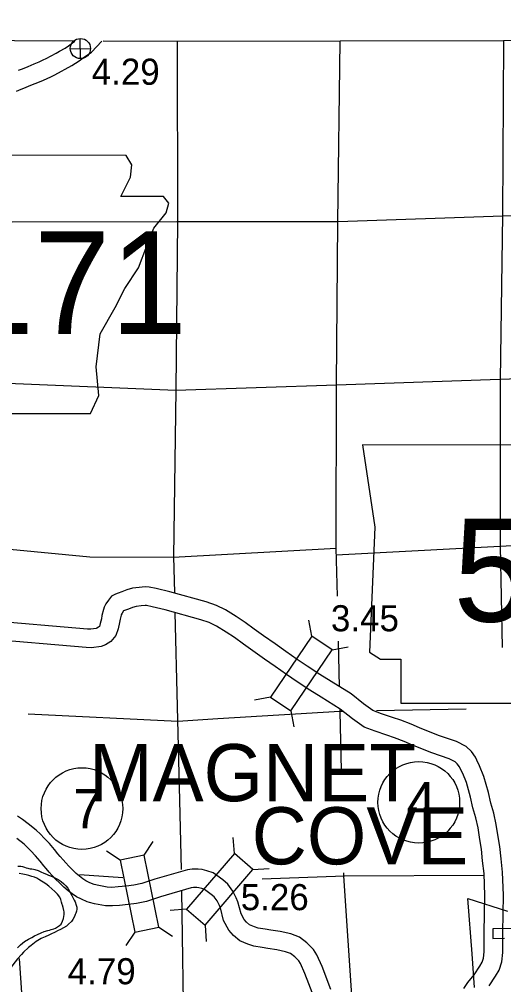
# Model space of a CAD drawing. Extents: x 369523 to 838377, y 495025 to 936819.
# Drawn here: x 644076 to 659736, y 887609 to 918834 of the extents above; entities that cross this region are included whole.
import ezdxf

# ---------------------------------------------------------------- set-up
doc = ezdxf.new("R2010")
doc.units = 0
for name, color, linetype in [('22', 7, 'Continuous'), ('DSN_BRDG_Annotation', 7, 'Continuous'), ('DSN_DRFT_Common-Annotations', 7, 'Continuous'), ('DSN_DRFT_Common-Line', 7, 'Continuous'), ('DSN_DRFT_Junk-No-Plot', 7, 'Continuous'), ('Level 1', 7, 'Continuous'), ('Level 10', 7, 'Continuous'), ('Level 11', 7, 'Continuous'), ('Level 2', 7, 'Continuous'), ('Level 21', 7, 'Continuous'), ('Level 22', 7, 'Continuous'), ('Level 6', 7, 'Continuous')]:
    doc.layers.add(name, color=color, linetype=linetype)

msp = doc.modelspace()

# ---------------------------------------------------------------- linework, layer by layer
at = {"layer": '22'}
for points in [[(639541, 914438), (639941, 911773), (639763, 907732), (640118, 907510), (640784, 907510), (640784, 906089), (646380, 906089), (646646, 906666), (646558, 907598), (646691, 908664), (647179, 909508), (647490, 910130), (647934, 910796), (648201, 911507), (648423, 912084), (648822, 912572), (648911, 912883), (648734, 913105), (647357, 913105), (647668, 913727), (647712, 914127), (647528, 914434)], [(655173, 905068), (655572, 902403), (655395, 898362), (655750, 898140), (656416, 898140), (656416, 896719), (662012, 896719), (662278, 897296), (662189, 898229), (662323, 899295), (662811, 900138), (663122, 900760), (663566, 901426), (663832, 902137), (664055, 902714), (664454, 903203), (664543, 903513), (664365, 903735), (662989, 903735), (663300, 904357), (663344, 904757), (663160, 905064)]]:
    msp.add_lwpolyline(points, close=True, dxfattribs=at)
at = {"layer": 'DSN_DRFT_Common-Annotations'}
for p, q in [((646058, 917562), (646043, 918213)), ((645725, 917880), (646376, 917895))]:
    msp.add_line(p, q, dxfattribs=at)
msp.add_circle((646051, 917888), 326, dxfattribs=at)
at = {"layer": 'DSN_DRFT_Common-Line'}
for centre in [(646101, 893305), (656992, 893507)]:
    msp.add_circle(centre, 1320, dxfattribs=at)
at = {"layer": 'Level 1'}
for points in [[(645269, 917739), (645370, 917808), (645554, 917900), (645662, 917976), (645792, 918071), (645876, 918130)], [(645775, 917343), (646011, 917488), (646143, 917584), (646405, 917771), (646745, 918131)], [(644052, 917189), (644176, 917236), (644357, 917312), (644551, 917391), (644716, 917458), (644850, 917519), (644942, 917567), (645269, 917739)], [(643984, 916511), (644136, 916574), (644274, 916632), (644398, 916678), (644586, 916757), (644778, 916835), (644953, 916906), (645114, 916980), (645227, 917039), (645775, 917343)], [(659265, 887577), (659471, 887889), (659587, 888081), (659678, 888348), (659703, 888647), (659710, 889295), (659728, 890502), (659701, 891248), (659653, 891680), (659609, 892077), (659558, 892395), (659496, 892791), (659415, 893157), (659324, 893482), (659247, 893823), (659099, 894348), (658958, 894691), (658871, 894867), (658820, 894969), (658693, 895149), (658520, 895315), (658208, 895470), (657628, 895670), (657018, 895916), (656744, 896033), (656412, 896164), (656141, 896252), (655785, 896372), (655510, 896477), (655204, 896689), (654803, 897012), (654158, 897417), (653795, 897646), (653384, 897908), (653055, 898132), (652697, 898388), (652345, 898631), (651975, 898895), (651674, 899108), (651379, 899327), (651085, 899523), (650737, 899729), (650453, 899875), (650119, 899989), (648946, 900313), (648503, 900420), (648276, 900465), (648145, 900477), (647951, 900460), (647739, 900431), (647548, 900382), (647394, 900321), (647268, 900274), (647186, 900243), (647054, 900173), (646954, 900047), (646874, 899923), (646824, 899817), (646796, 899748), (646746, 899554), (646729, 899443), (646691, 899287), (646663, 899200), (646638, 899170), (646586, 899138), (646562, 899128), (646386, 899104), (646279, 899111), (643003, 899392)], [(658448, 887488), (658579, 887678), (658779, 887930), (658964, 888210), (659039, 888335), (659086, 888472), (659103, 888675), (659110, 889302), (659127, 890496), (659102, 891204), (659056, 891614), (659015, 891997), (658965, 892301), (658906, 892680), (658833, 893011), (658742, 893335), (658665, 893675), (658531, 894152), (658411, 894443), (658333, 894600), (658304, 894660), (658236, 894756), (658170, 894819), (657976, 894916), (657418, 895107), (656788, 895362), (656516, 895478), (656210, 895599), (655953, 895682), (655582, 895807), (655228, 895942), (654845, 896209), (654454, 896522), (653838, 896909), (653473, 897139), (653054, 897407), (652712, 897639), (652352, 897897), (652000, 898140), (651628, 898406), (651322, 898622), (651034, 898836), (650766, 899015), (650448, 899204), (650218, 899321), (649942, 899415), (648796, 899732), (648374, 899834), (648191, 899871), (648145, 899874), (648017, 899863), (647854, 899841), (647735, 899811), (647609, 899760), (647477, 899712), (647444, 899699), (647442, 899697), (647399, 899630), (647374, 899577), (647368, 899562), (647335, 899433), (647318, 899326), (647269, 899124), (647198, 898904), (647037, 898712), (646861, 898602), (646719, 898544), (646409, 898502), (646236, 898512), (642938, 898796)]]:
    msp.add_lwpolyline(points, dxfattribs=at)
at = {"layer": 'Level 10'}
for points in [[(644019, 888797), (644117, 888895), (644239, 889005), (644372, 889079), (644479, 889139), (644570, 889188), (644659, 889236), (644778, 889290), (644876, 889331), (644999, 889359), (645055, 889376), (645105, 889391), (645194, 889416), (645250, 889441), (645309, 889480), (645372, 889527), (645424, 889572), (645474, 889663), (645501, 889748), (645512, 889814), (645521, 889878), (645526, 889961), (645519, 890013), (645490, 890104), (645470, 890180), (645464, 890206), (645445, 890274), (645420, 890366), (645384, 890437), (645309, 890542), (645222, 890627), (645126, 890710), (645035, 890793), (644930, 890875), (644710, 891008), (644640, 891053), (644569, 891082), (644485, 891109), (644382, 891143), (644294, 891164), (644194, 891182), (644071, 891208)], [(644024, 891448), (644130, 891440), (644178, 891434), (644246, 891411), (644301, 891392), (644347, 891375), (644381, 891363), (644427, 891356), (644479, 891355), (644531, 891350), (644577, 891336), (644686, 891302), (644776, 891261), (644873, 891217), (644951, 891184), (645024, 891155), (645080, 891134), (645158, 891099), (645227, 891066), (645330, 891013), (645429, 890947), (645510, 890876), (645577, 890809), (645642, 890726), (645689, 890654), (645734, 890571), (645777, 890489), (645819, 890410), (645854, 890340), (645882, 890285), (645918, 890183), (645931, 890121), (645932, 890051), (645921, 889991), (645900, 889922), (645883, 889882), (645856, 889811), (645809, 889718), (645758, 889650), (645668, 889562), (645605, 889505), (645506, 889443), (645403, 889390), (645315, 889346), (645238, 889311), (645093, 889248)], [(645093, 889248), (645025, 889215), (644908, 889161), (644801, 889116), (644779, 889099), (644623, 889007), (644459, 888882), (644376, 888813), (644216, 888664), (644142, 888585), (644018, 888442), (643941, 888347), (643869, 888252), (643732, 888067), (643652, 887958), (643600, 887819), (643573, 887734), (643535, 887625), (643512, 887533)]]:
    msp.add_lwpolyline(points, dxfattribs=at)
at = {"layer": 'Level 11'}
for points in [[(654152, 887459), (653862, 888200), (653700, 888573), (653591, 888752), (653376, 888964), (653133, 889148), (652854, 889250), (652510, 889331), (652209, 889374), (652023, 889410), (651802, 889440), (651675, 889484), (651522, 889545), (651425, 889628), (651345, 889716), (651244, 889906), (651145, 890286), (651090, 890418), (650984, 890629), (650821, 890856), (650653, 891001), (650338, 891227), (650141, 891296), (649986, 891331), (649854, 891349), (649667, 891349), (649508, 891328), (648455, 891019), (648035, 890877), (647774, 890824), (647534, 890797), (647268, 890772), (647067, 890758), (646920, 890760), (646642, 890813), (646499, 890853), (646463, 890862), (646336, 890917), (646229, 890970), (646129, 891038), (646024, 891115), (645918, 891205), (645804, 891316), (645678, 891441), (645579, 891548), (645494, 891643), (645398, 891760), (645320, 891846), (645209, 891981), (645047, 892179), (644882, 892350), (644763, 892477), (644625, 892610), (644366, 892814), (644179, 892954), (644020, 893065)], [(653623, 887165), (653307, 887971), (653167, 888296), (653117, 888377), (652983, 888509), (652843, 888615), (652682, 888674), (652398, 888741), (652110, 888782), (651926, 888817), (651661, 888854), (651466, 888922), (651210, 889023), (651005, 889197), (650850, 889370), (650681, 889686), (650575, 890095), (650545, 890168), (650469, 890317), (650375, 890448), (650281, 890529), (650058, 890689), (649976, 890718), (649878, 890740), (649813, 890749), (649705, 890749), (649632, 890740), (648636, 890446), (648192, 890297), (647868, 890231), (647595, 890200), (647318, 890174), (647084, 890157), (646859, 890161), (646507, 890228), (646344, 890273), (646267, 890293), (646083, 890373), (645927, 890450), (645782, 890548), (645651, 890645), (645515, 890761), (645383, 890888), (645246, 891024), (645135, 891145), (645038, 891253), (644944, 891368), (644866, 891454), (644746, 891601), (644598, 891780), (644447, 891937), (644335, 892056), (644231, 892157), (644000, 892338)]]:
    msp.add_lwpolyline(points, dxfattribs=at)
at = {"layer": 'Level 2'}
for points in [[(658796, 887517), (658712, 888610), (658574, 890400), (659859, 889988)], [(659979, 889423), (659384, 889416), (659386, 889173), (659387, 889107), (659762, 889114)]]:
    msp.add_lwpolyline(points, dxfattribs=at)
at = {"layer": 'Level 21'}
for p, q in [((653532, 898881), (653432, 899400)), ((654187, 898437), (654706, 898537)), ((652199, 896914), (651680, 896815)), ((652854, 896470), (652954, 895952)), ((648110, 891799), (648401, 892239)), ((651030, 891848), (650991, 892374)), ((647334, 891640), (646893, 891931)), ((651630, 891331), (652157, 891370)), ((649479, 890048), (648953, 890008)), ((647810, 889312), (647519, 888872)), ((648586, 889471), (649026, 889180)), ((650080, 889531), (650119, 889004))]:
    msp.add_line(p, q, dxfattribs=at)
for points in [[(653532, 898881), (652199, 896914), (652854, 896470), (654187, 898437)], [(647334, 891640), (647810, 889312), (648586, 889471), (648110, 891799)], [(651030, 891848), (649479, 890048), (650080, 889531), (651630, 891331)]]:
    msp.add_lwpolyline(points, close=True, dxfattribs=at)
at = {"layer": 'Level 22'}
for points in [[(649176, 918116), (649188, 912291), (649133, 906846), (649056, 901446), (649088, 900298)], [(654322, 901726), (654331, 907012), (654371, 912283), (654446, 918124)], [(659725, 918140), (659697, 912511), (659624, 907177), (659623, 901793)], [(670351, 912810), (664932, 912677), (659710, 912471), (654381, 912279), (649169, 912279), (643845, 912269)], [(670304, 907639), (664925, 907367), (659610, 907181), (654331, 907002), (649137, 906828), (643693, 907052)], [(654322, 901515), (664916, 902071), (669986, 902305)], [(659623, 901793), (659691, 898519)], [(643768, 901698), (646352, 901451), (649047, 901440), (654322, 901726)], [(654359, 900181), (654323, 901726)], [(649103, 899647), (649260, 893562), (649310, 891337)], [(654428, 897244), (654394, 898716)], [(654491, 894539), (654447, 896450), (654446, 896497)], [(658522, 896525), (655627, 896467)], [(649202, 896118), (644358, 896357)], [(654552, 896446), (654435, 896443), (650491, 896212), (649202, 896118)], [(654849, 886937), (654570, 891129), (654568, 891226)], [(647419, 891062), (646026, 891162)], [(659079, 891140), (654590, 891118), (651932, 891018)], [(649323, 890632), (649393, 885593)], [(644197, 886717), (644078, 888461)]]:
    msp.add_lwpolyline(points, dxfattribs=at)
at = {"layer": 'Level 6'}
for points in [[(664922, 921003), (664932, 918184), (659725, 918140), (654446, 918124), (649176, 918116), (646792, 918127)], [(645828, 918131), (643923, 918139), (640230, 918286)]]:
    msp.add_lwpolyline(points, dxfattribs=at)

# ---------------------------------------------------------------- texts
at = {"layer": '22'}
for s, p in [('171', (642073, 908652)), ('51', (658110, 899352))]:
    msp.add_text(s, height=3326.4, dxfattribs=at).set_placement(p)
at = {"layer": 'DSN_BRDG_Annotation'}
msp.add_text('4.29', height=844.8, dxfattribs=at).set_placement((646416, 916716))
at = {"layer": 'DSN_DRFT_Common-Annotations'}
for s, p in [('MAGNET', (646328, 893543)), ('COVE', (651587, 891501))]:
    msp.add_text(s, height=1848, dxfattribs=at).set_placement(p)
at = {"layer": 'DSN_DRFT_Common-Line'}
for s, p in [('4', (656598, 892898)), ('7', (645817, 892671))]:
    msp.add_text(s, height=1267, dxfattribs=at).set_placement(p)
at = {"layer": 'DSN_DRFT_Junk-No-Plot'}
for s, p in [('3.45', (654151, 899039)), ('5.26', (651235, 890019)), ('4.79', (645640, 887622))]:
    msp.add_text(s, height=844.8, dxfattribs=at).set_placement(p)

doc.saveas('drawing.dxf')
